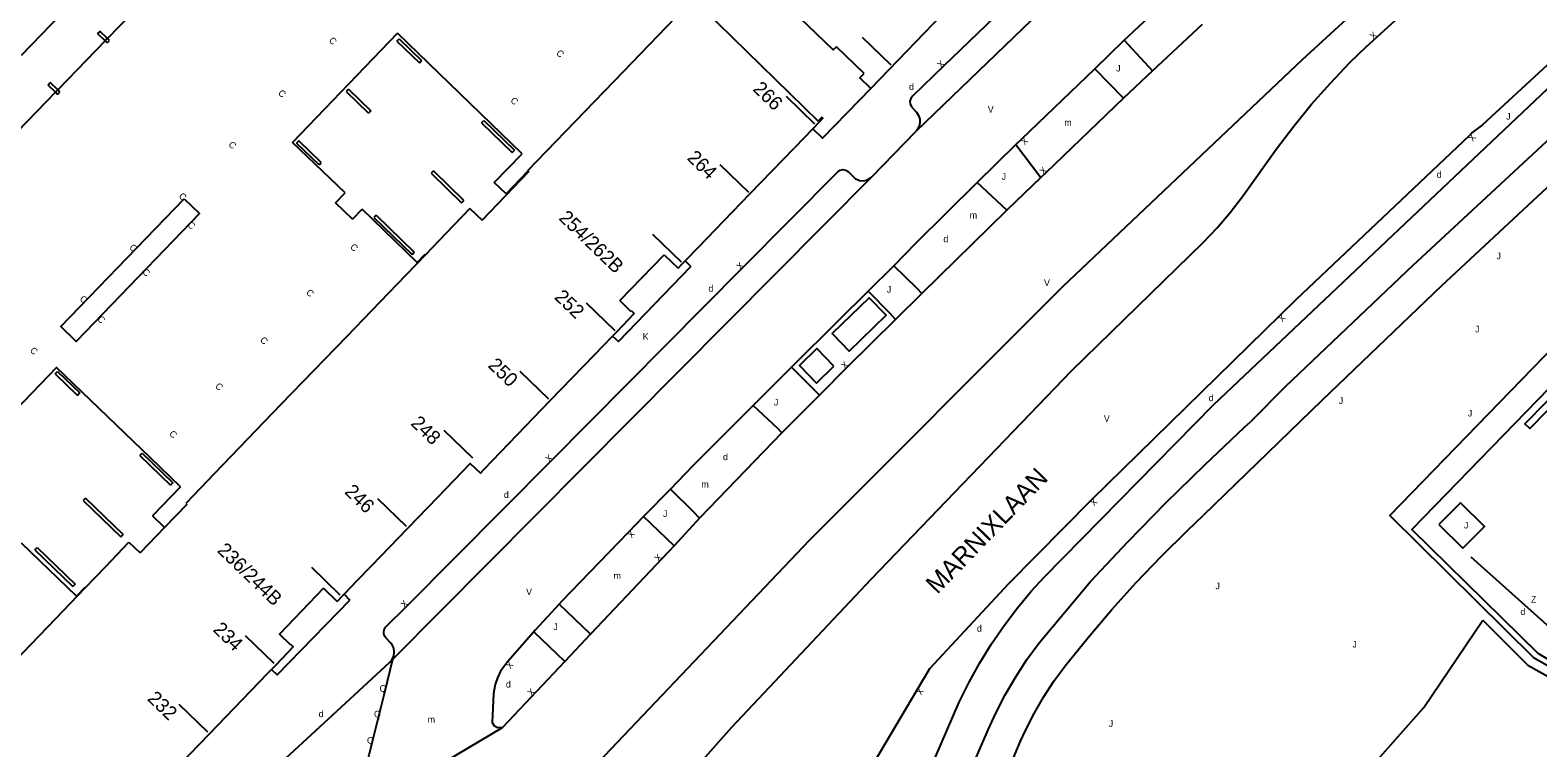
# Model space of a CAD drawing. Extents: x 134999 to 136502, y 457398 to 459002.
# Drawn here: x 135185.3 to 135299.1, y 457943.8 to 457998 of the extents above; entities that cross this region are included whole.
import ezdxf

# ---------------------------------------------------------------- set-up
doc = ezdxf.new("R2010")
doc.units = 0
for name, color, linetype in [('RI_DGTB_15', 7, 'Continuous'), ('RI_DGTB_19', 7, 'Continuous'), ('RI_DGTB_2', 7, 'Continuous'), ('RI_DGTB_29', 7, 'Continuous'), ('RI_DGTB_30', 7, 'Continuous'), ('RI_DGTB_31', 7, 'Continuous'), ('RI_DGTB_32', 7, 'Continuous'), ('RI_DGTB_36', 7, 'Continuous'), ('RI_DGTB_37', 7, 'Continuous'), ('RI_DGTB_43', 7, 'Continuous'), ('RI_DGTB_48', 7, 'Continuous'), ('RI_DGTB_49', 7, 'Continuous'), ('RI_DGTB_53', 7, 'Continuous'), ('RI_DGTB_55', 7, 'Continuous'), ('RI_DGTB_6', 7, 'Continuous'), ('RI_DGTB_7', 7, 'Continuous')]:
    doc.layers.add(name, color=color, linetype=linetype)

msp = doc.modelspace()

# ---------------------------------------------------------------- linework, layer by layer
at = {"layer": 'RI_DGTB_15'}
for p, q in [((135250.261, 457995.309), (135248.105, 457997.395)), ((135244.507, 457990.866), (135242.351, 457992.952)), ((135239.507, 457985.693), (135237.351, 457987.779)), ((135234.417, 457980.428), (135232.26, 457982.513)), ((135229.417, 457975.255), (135227.26, 457977.34)), ((135224.417, 457970.083), (135222.26, 457972.168)), ((135218.663, 457965.64), (135216.506, 457967.725)), ((135213.663, 457960.467), (135211.506, 457962.552)), ((135208.664, 457955.295), (135206.507, 457957.38)), ((135203.664, 457950.122), (135201.508, 457952.208)), ((135198.664, 457944.95), (135196.508, 457947.036))]:
    msp.add_line(p, q, dxfattribs=at)
at = {"layer": 'RI_DGTB_19'}
for points in [[(135273.142, 457929.253), (135281.462, 457937.569), (135285.819, 457941.55), (135290.477, 457946.808), (135294.918, 457953.388)], [(135294.918, 457953.388), (135298.334, 457950.012), (135303.058, 457947.359), (135305.728, 457946.835), (135308.395, 457947.388), (135310.574, 457949.061), (135312.091, 457950.876)]]:
    msp.add_lwpolyline(points, dxfattribs=at)
at = {"layer": 'RI_DGTB_2'}
for p, q in [((135236.087, 457999.537), (135244.751, 457991.087)), ((135205.066, 457989.47), (135212.983, 457997.723)), ((135222.4, 457988.63), (135212.983, 457997.723)), ((135244.341, 457990.513), (135242.952, 457989.076)), ((135209.035, 457985.66), (135205.066, 457989.47)), ((135220.295, 457986.45), (135222.4, 457988.63)), ((135219.371, 457983.603), (135222.9, 457987.271)), ((135221.18, 457985.596), (135222.847, 457987.322)), ((135222.821, 457987.347), (135222.847, 457987.322)), ((135222.847, 457987.322), (135222.9, 457987.271)), ((135221.18, 457985.596), (135220.295, 457986.45)), ((135208.313, 457984.912), (135209.035, 457985.66)), ((135209.586, 457983.683), (135208.313, 457984.912)), ((135209.586, 457983.683), (135210.308, 457984.431)), ((135214.466, 457980.415), (135210.308, 457984.431)), ((135218.455, 457984.481), (135219.371, 457983.603)), ((135214.466, 457980.415), (135215.07, 457981.041)), ((135215.103, 457981.002), (135215.07, 457981.041)), ((135229.764, 457977.539), (135233.126, 457980.998)), ((135233.126, 457980.998), (135234.173, 457979.98)), ((135229.764, 457977.539), (135230.581, 457976.746)), ((135230.581, 457976.746), (135230.63, 457976.796)), ((135196.597, 457963.475), (135194.35, 457965.648)), ((135196.597, 457963.475), (135194.484, 457961.29)), ((135197.073, 457962.133), (135195.403, 457960.4)), ((135196.993, 457962.209), (135197.047, 457962.157)), ((135197.047, 457962.157), (135197.073, 457962.133)), ((135195.403, 457960.4), (135194.484, 457961.29)), ((135195.403, 457960.4), (135193.548, 457958.475)), ((135192.712, 457959.28), (135193.548, 457958.475)), ((135189.372, 457955.868), (135188.745, 457955.222)), ((135204.91, 457951.597), (135204.872, 457951.558))]:
    msp.add_line(p, q, dxfattribs=at)
for points in [[(135246.12, 457996.707), (135245.882, 457996.478), (135240.929, 458001.266), (135239.283, 458002.851)], [(135194.614, 458000.981), (135191.084, 457997.328)], [(135184.593, 457996.072), (135188.341, 457999.954)], [(135230.038, 457994.847), (135235.295, 458000.309)], [(135255.103, 458000.144), (135254.799, 457999.836), (135248.716, 457993.545)], [(135191.071, 457997.315), (135190.91, 457997.148)], [(135191.084, 457997.328), (135191.071, 457997.315)], [(135190.91, 457997.148), (135187.33, 457993.444)], [(135248.215, 457994.682), (135246.12, 457996.707)], [(135224.96, 457989.57), (135230.038, 457994.847)], [(135248.716, 457993.545), (135247.893, 457994.354), (135248.215, 457994.682)], [(135187.156, 457993.264), (135183.575, 457989.558)], [(135187.321, 457993.435), (135187.156, 457993.264)], [(135187.33, 457993.444), (135187.321, 457993.435)], [(135248.716, 457993.545), (135245.066, 457989.807), (135244.341, 457990.513)], [(135244.824, 457991.016), (135244.341, 457990.513)], [(135245.032, 457991.379), (135244.751, 457991.087)], [(135245.032, 457991.379), (135245.103, 457991.306), (135244.824, 457991.016)], [(135222.821, 457987.347), (135224.96, 457989.57)], [(135239.599, 457985.604), (135242.952, 457989.076)], [(135235.706, 457981.572), (135239.599, 457985.604)], [(135218.455, 457984.481), (135216.643, 457982.6)], [(135216.643, 457982.6), (135215.103, 457981.002)], [(135235.706, 457981.572), (135234.704, 457980.533)], [(135215.103, 457981.002), (135212.899, 457978.715)], [(135229.23, 457974.852), (135229.67, 457974.45), (135235.132, 457980.117)], [(135234.173, 457979.98), (135234.514, 457980.335)], [(135234.514, 457980.335), (135234.704, 457980.533)], [(135234.704, 457980.533), (135235.132, 457980.117)], [(135212.899, 457978.715), (135209.156, 457974.831)], [(135230.63, 457976.796), (135230.86, 457976.571)], [(135230.86, 457976.571), (135229.519, 457975.157)], [(135209.156, 457974.831), (135204.164, 457969.65)], [(135224.525, 457969.978), (135227.86, 457973.439), (135229.23, 457974.852)], [(135229.519, 457975.157), (135229.23, 457974.852)], [(135194.35, 457965.648), (135187.24, 457972.488), (135183.513, 457968.617), (135179.338, 457964.283)], [(135219.532, 457964.8), (135220.791, 457966.103), (135224.525, 457969.978)], [(135204.164, 457969.65), (135199.173, 457964.471)], [(135199.173, 457964.471), (135196.993, 457962.209)], [(135213.777, 457960.357), (135216.021, 457962.68), (135218.484, 457965.225), (135219.246, 457964.503), (135219.532, 457964.8)], [(135209.941, 457956.388), (135211.018, 457957.501), (135213.777, 457960.357)], [(135188.745, 457955.222), (135184.601, 457959.208)], [(135190.933, 457957.426), (135192.712, 457959.28)], [(135189.406, 457955.835), (135190.933, 457957.426)], [(135209.941, 457956.388), (135208.956, 457955.363)], [(135187.196, 457953.532), (135189.406, 457955.835)], [(135189.406, 457955.835), (135189.372, 457955.868)], [(135207.396, 457955.819), (135204.065, 457952.335), (135204.872, 457951.558)], [(135207.396, 457955.819), (135208.42, 457954.817)], [(135208.78, 457955.183), (135208.42, 457954.817)], [(135208.956, 457955.363), (135208.78, 457955.183)], [(135208.956, 457955.363), (135209.378, 457954.92)], [(135203.484, 457949.682), (135203.911, 457949.282), (135209.378, 457954.92)], [(135183.462, 457949.641), (135187.196, 457953.532)], [(135204.91, 457951.597), (135205.117, 457951.383), (135203.792, 457950.003)], [(135198.79, 457944.828), (135203.172, 457949.373), (135203.484, 457949.682)], [(135203.792, 457950.003), (135203.484, 457949.682)], [(135193.797, 457939.649), (135195.034, 457940.932), (135198.79, 457944.828)]]:
    msp.add_lwpolyline(points, dxfattribs=at)
at = {"layer": 'RI_DGTB_32'}
for points in [[(135248.59, 457977.741), (135245.811, 457975.041), (135247.092, 457973.722), (135249.872, 457976.422), (135248.59, 457977.741)], [(135245.931, 457972.588), (135244.648, 457973.907), (135243.33, 457972.625), (135244.613, 457971.306), (135245.931, 457972.588)], [(135303.509, 457973.019), (135298.466, 457967.879), (135298.109, 457968.229), (135303.152, 457973.369), (135303.509, 457973.019)]]:
    msp.add_lwpolyline(points, dxfattribs=at)
at = {"layer": 'RI_DGTB_48'}
msp.add_lwpolyline([(135320.943, 457985.639), (135316.022, 457990.283), (135287.899, 457961.311), (135298.759, 457950.576), (135303.303, 457948.024), (135305.724, 457947.549), (135308.096, 457948.041), (135310.086, 457949.569), (135311.527, 457951.292)], dxfattribs=at)
at = {"layer": 'RI_DGTB_49'}
msp.add_line((135302.725, 457950.393), (135294.044, 457958.163), dxfattribs=at)
at = {"layer": 'RI_DGTB_53'}
for p, q in [((135267.852, 457997.197), (135269.987, 457994.887)), ((135265.624, 457995.037), (135267.808, 457992.812)), ((135269.987, 457994.887), (135267.808, 457992.812)), ((135251.786, 457992.173), (135252.166, 457991.757)), ((135248.799, 457986.885), (135252.134, 457990.327)), ((135259.681, 457989.313), (135261.549, 457986.826)), ((135247.019, 457987.282), (135247.534, 457986.753)), ((135258.986, 457984.358), (135256.753, 457986.447)), ((135258.931, 457984.305), (135252.562, 457978.079)), ((135250.466, 457980.16), (135252.113, 457981.867)), ((135248.527, 457978.249), (135250.466, 457980.16)), ((135289.634, 457980.173), (135280.019, 457971.047)), ((135252.562, 457978.079), (135250.579, 457976.099)), ((135291.807, 457978.646), (135282.777, 457969.988)), ((135239.842, 457969.603), (135242.739, 457972.496)), ((135242.739, 457972.496), (135244.852, 457970.395)), ((135280.019, 457971.047), (135277.389, 457968.388)), ((135244.852, 457970.395), (135241.999, 457967.552)), ((135282.777, 457969.988), (135273.825, 457961.313)), ((135241.999, 457967.552), (135235.798, 457961.103)), ((135233.872, 457959.013), (135231.57, 457961.217)), ((135235.798, 457961.103), (135233.872, 457959.013)), ((135233.872, 457959.013), (135227.552, 457952.333)), ((135212.489, 457951.672), (135212.112, 457952.058)), ((135227.552, 457952.333), (135225.631, 457950.287)), ((135221.329, 457950.272), (135221.094, 457949.985)), ((135220.241, 457947.826), (135220.129, 457945.69)), ((135210.106, 457938.88), (135220.903, 457945.299))]:
    msp.add_line(p, q, dxfattribs=at)
for points in [[(135283.748, 458023.677), (135273.511, 458013.838), (135266.459, 458007.049), (135254.206, 457995.232), (135251.868, 457992.981)], [(135286.177, 458023.305), (135286.064, 458022.997), (135284.686, 458021.668), (135274.766, 458012.118), (135255.507, 457993.572), (135252.134, 457990.327)], [(135197.385, 457913.095), (135202.138, 457916.799), (135204.24, 457918.512), (135206.29, 457920.287), (135208.287, 457922.121), (135210.229, 457924.013), (135224.729, 457939.075), (135244.129, 457959.465), (135263.216, 457978.594), (135281.309, 457995.733), (135296.421, 458009.621)], [(135206.955, 457905.049), (135212.592, 457913.238), (135217.253, 457919.752), (135225.611, 457930.272), (135233.639, 457940.162), (135238.232, 457945.313), (135248.755, 457956.499), (135263.902, 457972.252), (135273.809, 457981.927), (135274.863, 457983.03), (135275.858, 457984.186), (135276.791, 457985.394), (135279.359, 457989), (135280.65, 457990.703), (135282.004, 457992.356), (135283.418, 457993.957), (135284.892, 457995.505), (135286.115, 457996.705), (135297.99, 458007.534), (135298.197, 458007.685), (135297.972, 458007.93)], [(135267.852, 457997.197), (135271.567, 458000.692)], [(135304.993, 458000.123), (135294.905, 457990.805), (135294.1, 457990.209), (135293.906, 457989.974), (135280.817, 457977.592), (135265.355, 457962.473), (135259.111, 457956.156), (135253.159, 457949.73)], [(135251.463, 457938.756), (135252.072, 457939.753), (135252.588, 457940.747), (135255.4, 457947.209), (135256.14, 457948.713), (135256.951, 457950.18), (135257.831, 457951.606), (135258.778, 457952.989), (135259.79, 457954.325), (135260.864, 457955.611), (135261.815, 457956.653), (135274.606, 457969.672), (135302.146, 457995.737), (135303.097, 457996.534), (135304.097, 457997.267), (135305.143, 457997.935), (135306.448, 457998.641)], [(135273.728, 457998.372), (135269.987, 457994.887)], [(135265.624, 457995.037), (135267.852, 457997.197)], [(135289.634, 457980.173), (135303.913, 457993.414), (135304.679, 457994.006), (135305.677, 457994.687), (135306.719, 457995.3), (135307.798, 457995.843), (135308.912, 457996.314), (135310.054, 457996.71), (135311.219, 457997.029), (135312.404, 457997.271), (135313.601, 457997.434), (135314.807, 457997.517), (135316.016, 457997.521), (135317.222, 457997.444), (135318.42, 457997.288), (135319.606, 457997.053), (135320.216, 457996.904)], [(135259.681, 457989.313), (135260.123, 457989.743), (135265.624, 457995.037)], [(135291.807, 457978.646), (135309.234, 457994.86)], [(135251.868, 457992.981), (135251.735, 457992.808), (135251.672, 457992.599), (135251.688, 457992.382), (135251.786, 457992.173)], [(135267.808, 457992.812), (135261.94, 457987.183), (135261.549, 457986.826)], [(135252.166, 457991.757), (135252.327, 457991.519), (135252.418, 457991.245), (135252.429, 457990.957), (135252.362, 457990.677), (135252.22, 457990.427), (135252.134, 457990.327)], [(135256.753, 457986.447), (135259.681, 457989.313)], [(135212.088, 457952.884), (135213.695, 457954.47), (135224.62, 457965.462), (135239.04, 457980.007), (135246.227, 457987.266)], [(135246.227, 457987.266), (135246.409, 457987.385), (135246.619, 457987.429), (135246.831, 457987.394), (135247.019, 457987.282)], [(135248.799, 457986.885), (135234.209, 457972.182), (135212.611, 457950.429), (135212.011, 457947.939), (135210.607, 457942.304), (135210.144, 457940.31)], [(135247.534, 457986.753), (135247.87, 457986.616), (135248.146, 457986.589), (135248.418, 457986.641), (135248.664, 457986.769), (135248.799, 457986.885)], [(135252.113, 457981.867), (135256.753, 457986.447)], [(135261.549, 457986.826), (135258.986, 457984.358)], [(135258.986, 457984.358), (135258.931, 457984.305)], [(135252.562, 457978.079), (135252.187, 457978.468), (135250.466, 457980.16)], [(135242.739, 457972.496), (135246.309, 457976.062), (135248.527, 457978.249)], [(135250.579, 457976.099), (135250.184, 457976.565), (135248.527, 457978.249)], [(135250.579, 457976.099), (135246.941, 457972.505), (135244.852, 457970.395)], [(135233.589, 457963.281), (135235.317, 457965.084), (135239.842, 457969.603)], [(135241.999, 457967.552), (135241.718, 457967.856), (135239.842, 457969.603)], [(135265.304, 457956.311), (135268.126, 457959.309), (135271.006, 457962.252), (135273.942, 457965.139), (135276.934, 457967.968), (135277.389, 457968.388)], [(135233.589, 457963.281), (135231.57, 457961.217)], [(135235.798, 457961.103), (135235.347, 457961.589), (135233.589, 457963.281)], [(135231.57, 457961.217), (135230.426, 457960.048), (135227.489, 457956.994)], [(135263.401, 457949.949), (135265.126, 457952.102), (135266.911, 457954.201), (135268.756, 457956.249), (135270.66, 457958.241), (135272.621, 457960.178), (135273.825, 457961.313)], [(135227.489, 457956.994), (135225.404, 457954.839), (135225.185, 457954.601)], [(135238.633, 457921.828), (135240.786, 457924.204), (135250.313, 457933.039), (135251.443, 457934.228), (135252.376, 457935.335), (135253.248, 457936.491), (135254.053, 457937.694), (135254.792, 457938.94), (135255.46, 457940.224), (135257.585, 457945.111), (135258.162, 457946.378), (135258.876, 457947.766), (135259.661, 457949.115), (135260.514, 457950.423), (135261.433, 457951.685), (135265.304, 457956.311)], [(135225.185, 457954.601), (135223.384, 457952.636), (135223.276, 457952.512)], [(135227.552, 457952.333), (135225.185, 457954.601)], [(135212.112, 457952.058), (135211.992, 457952.241), (135211.944, 457952.458), (135211.975, 457952.678), (135212.088, 457952.884)], [(135212.4, 457950.219), (135212.584, 457950.44), (135212.701, 457950.704), (135212.741, 457950.99), (135212.702, 457951.275), (135212.586, 457951.539), (135212.489, 457951.672)], [(135223.276, 457952.512), (135221.329, 457950.272)], [(135225.631, 457950.287), (135223.276, 457952.512)], [(135181.136, 457921.358), (135189.111, 457928.766), (135199.753, 457938.559), (135208.742, 457946.839), (135212.4, 457950.219)], [(135221.094, 457949.985), (135220.772, 457949.537), (135220.525, 457949.055), (135220.352, 457948.541), (135220.255, 457948.008), (135220.241, 457947.826)], [(135225.631, 457950.287), (135220.903, 457945.299)], [(135253.159, 457949.73), (135252.195, 457948.124), (135248.16, 457941.322)], [(135255.52, 457935.159), (135256.332, 457936.374), (135257.116, 457937.691), (135257.83, 457939.048), (135260.028, 457944.252), (135260.396, 457945.07), (135261.045, 457946.351), (135261.764, 457947.594), (135262.55, 457948.795), (135263.401, 457949.949)], [(135220.903, 457945.299), (135220.532, 457945.267), (135220.319, 457945.4), (135220.129, 457945.69)]]:
    msp.add_lwpolyline(points, dxfattribs=at)
at = {"layer": 'RI_DGTB_55'}
for points in [[(135317.133, 457988.607), (135289.558, 457960.247), (135299.091, 457950.917), (135302.563, 457948.842)], [(135291.617, 457960.624), (135293.431, 457958.839), (135295.047, 457960.481), (135293.234, 457962.266), (135291.617, 457960.624)]]:
    msp.add_lwpolyline(points, dxfattribs=at)
at = {"layer": 'RI_DGTB_6'}
msp.add_lwpolyline([(135196.88, 457985.219), (135198.039, 457984.103), (135188.727, 457974.451), (135187.568, 457975.59), (135196.88, 457985.219)], dxfattribs=at)
at = {"layer": 'RI_DGTB_7'}
for p, q in [((135190.91, 457997.148), (135190.343, 457997.695)), ((135191.084, 457997.328), (135190.517, 457997.875)), ((135191.237, 457997.181), (135191.084, 457997.328)), ((135212.945, 457997.131), (135213.119, 457997.311)), ((135213.119, 457997.311), (135214.808, 457995.677)), ((135191.063, 457997), (135190.91, 457997.148)), ((135191.063, 457997), (135191.237, 457997.181)), ((135212.945, 457997.131), (135214.635, 457995.497)), ((135214.635, 457995.497), (135214.808, 457995.677)), ((135187.156, 457993.264), (135186.602, 457993.799)), ((135187.33, 457993.444), (135186.776, 457993.979)), ((135187.322, 457993.104), (135187.156, 457993.264)), ((135187.322, 457993.104), (135187.496, 457993.284)), ((135187.496, 457993.284), (135187.33, 457993.444)), ((135209.277, 457993.505), (135209.104, 457993.325)), ((135209.104, 457993.325), (135210.797, 457991.695)), ((135209.277, 457993.505), (135210.97, 457991.875)), ((135210.97, 457991.875), (135210.797, 457991.695)), ((135219.339, 457990.954), (135219.513, 457991.135)), ((135219.339, 457990.954), (135221.65, 457988.726)), ((135219.513, 457991.135), (135221.823, 457988.906)), ((135205.536, 457989.608), (135205.362, 457989.427)), ((135207.061, 457987.789), (135205.362, 457989.427)), ((135207.234, 457987.969), (135205.536, 457989.608)), ((135221.65, 457988.726), (135221.823, 457988.906)), ((135207.061, 457987.789), (135207.234, 457987.969)), ((135215.695, 457987.325), (135215.522, 457987.145)), ((135215.522, 457987.145), (135217.825, 457984.907)), ((135215.695, 457987.325), (135217.998, 457985.087)), ((135217.825, 457984.907), (135217.998, 457985.087)), ((135211.374, 457983.992), (135211.2, 457983.812)), ((135211.2, 457983.812), (135214.082, 457981.023)), ((135211.374, 457983.992), (135214.256, 457981.203)), ((135214.082, 457981.023), (135214.256, 457981.203)), ((135187.139, 457972.001), (135187.313, 457972.182)), ((135187.313, 457972.182), (135188.996, 457970.556)), ((135187.139, 457972.001), (135188.823, 457970.376)), ((135188.996, 457970.556), (135188.823, 457970.376)), ((135193.533, 457965.825), (135193.706, 457966.004)), ((135193.533, 457965.825), (135195.85, 457963.603)), ((135193.706, 457966.004), (135196.023, 457963.783)), ((135196.023, 457963.783), (135195.85, 457963.603)), ((135189.439, 457962.614), (135189.265, 457962.433)), ((135189.265, 457962.433), (135192.102, 457959.698)), ((135189.439, 457962.614), (135192.275, 457959.879)), ((135192.102, 457959.698), (135192.275, 457959.879)), ((135185.602, 457958.717), (135185.775, 457958.897)), ((135185.602, 457958.717), (135188.48, 457955.938)), ((135185.775, 457958.897), (135188.654, 457956.119)), ((135188.654, 457956.119), (135188.48, 457955.938))]:
    msp.add_line(p, q, dxfattribs=at)
for points in [[(135190.505, 457997.862), (135190.343, 457997.695)], [(135190.517, 457997.875), (135190.505, 457997.862)], [(135186.767, 457993.97), (135186.602, 457993.799)], [(135186.776, 457993.979), (135186.767, 457993.97)]]:
    msp.add_lwpolyline(points, dxfattribs=at)

# ---------------------------------------------------------------- texts
at = {"layer": 'RI_DGTB_29'}
for p in [(135251.604, 457993.439), (135291.45, 457986.807), (135254.201, 457981.938), (135236.462, 457978.201), (135274.232, 457969.94), (135237.56, 457965.485), (135221.018, 457962.633), (135297.767, 457953.786), (135256.733, 457952.534), (135221.17, 457948.314), (135207.032, 457946.077)]:
    msp.add_text('d', height=0.5, dxfattribs=at).set_placement(p)
at = {"layer": 'RI_DGTB_30'}
for rotation, p in [(42.13456, (135286.674, 457997.211)), (43.96288, (135254.026, 457995.058)), (224.16628, (135260.302, 457989.917)), (230.46146, (135294.065, 457990.167)), (43.80887, (135261.76, 457987.01)), (45.24828, (135238.864, 457979.829)), (224.09242, (135279.742, 457976.551)), (44.65158, (135246.764, 457972.329)), (45.17413, (135224.444, 457965.285)), (224.38011, (135265.533, 457962.648)), (226.353, (135230.599, 457960.229)), (46.22767, (135232.693, 457957.782)), (44.61098, (135213.517, 457954.294)), (228.77271, (135221.404, 457950.35)), (46.59238, (135223.115, 457947.627)), (239.03899, (135252.324, 457948.338))]:
    msp.add_text('X', height=0.5, rotation=rotation, dxfattribs=at).set_placement(p)
for s, p in [('V', (135257.553, 457991.728)), ('V', (135261.799, 457978.631)), ('K', (135231.504, 457974.575)), ('V', (135266.317, 457968.377)), ('V', (135222.698, 457955.289))]:
    msp.add_text(s, height=0.5, dxfattribs=at).set_placement(p)
at = {"layer": 'RI_DGTB_31'}
for s, p in [('J', (135267.247, 457994.837)), ('J', (135296.687, 457991.201)), ('J', (135258.602, 457986.654)), ('J', (135295.963, 457980.651)), ('J', (135249.931, 457978.129)), ('J', (135241.404, 457969.611)), ('J', (135284.051, 457969.724)), ('J', (135233.032, 457961.198)), ('J', (135274.744, 457955.729)), ('J', (135224.755, 457952.653)), ('Q', (135211.635, 457947.996)), ('Q', (135211.213, 457946.058)), ('J', (135266.686, 457945.343)), ('Q', (135210.682, 457944.078))]:
    msp.add_text(s, height=0.5, dxfattribs=at).set_placement(p)
for p in [(135294.341, 457975.132), (135293.801, 457968.782), (135293.501, 457960.322), (135285.081, 457951.332)]:
    msp.add_text('J', height=0.5, rotation=359.99973, dxfattribs=at).set_placement(p)
at = {"layer": 'RI_DGTB_32'}
msp.add_text('Z', height=0.5, dxfattribs=at).set_placement((135298.56, 457954.71))
at = {"layer": 'RI_DGTB_36'}
for s, rotation, p in [('266', 315.9712, (135239.75, 457993.444)), ('264', 315.9712, (135234.784, 457988.239)), ('254/262B', 315.9744, (135225.098, 457983.702)), ('252', 315.9744, (135224.77, 457977.725)), ('250', 315.9744, (135219.755, 457972.568)), ('248', 315.9744, (135213.929, 457968.194)), ('246', 315.9744, (135208.923, 457963.027)), ('236/244B', 315.9743, (135199.311, 457958.6)), ('234', 315.9712, (135198.994, 457952.617)), ('232', 315.9712, (135194.036, 457947.404))]:
    msp.add_text(s, height=1.054, rotation=rotation, dxfattribs=at).set_placement(p)
at = {"layer": 'RI_DGTB_37'}
msp.add_text('MARNIXLAAN', height=1.4, rotation=46.0091, dxfattribs=at).set_placement((135253.742, 457955.297))
at = {"layer": 'RI_DGTB_43'}
for p in [(135263.335, 457990.73), (135256.193, 457983.731), (135235.931, 457963.414), (135229.299, 457956.509), (135215.268, 457945.657)]:
    msp.add_text('m', height=0.5, rotation=0.16348, dxfattribs=at).set_placement(p)
at = {"layer": 'RI_DGTB_7'}
for p in [(135207.764, 457997.131), (135224.926, 457996.172), (135203.93, 457993.155), (135221.467, 457992.593), (135200.182, 457989.267), (135196.428, 457985.373), (135197.082, 457983.198), (135192.694, 457981.499), (135209.368, 457981.527), (135193.68, 457979.638), (135188.946, 457977.612), (135206.046, 457978.094), (135190.282, 457976.081), (135202.569, 457974.501), (135185.195, 457973.721), (135199.18, 457971.022), (135195.708, 457967.425)]:
    msp.add_text('C', height=0.5, rotation=316.80588, dxfattribs=at).set_placement(p)

doc.saveas('drawing.dxf')
